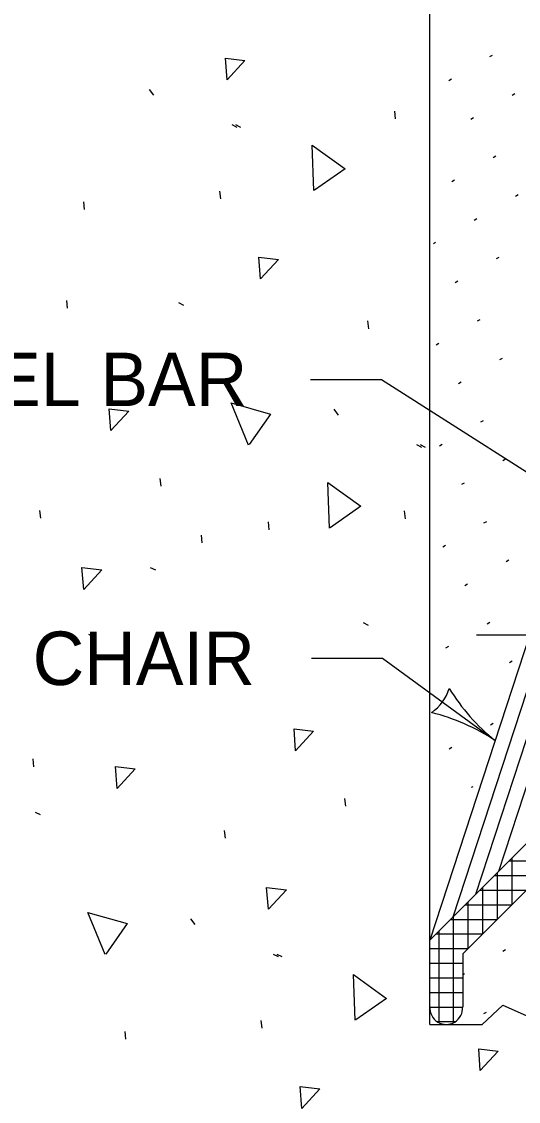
# Model space of a CAD drawing. Extents: x 49991.4 to 50021, y 49987.6 to 50011.4.
# Drawn here: x 50003.117 to 50003.675, y 49989.221 to 49990.433 of the extents above; entities that cross this region are included whole.
import ezdxf

# ---------------------------------------------------------------- set-up
doc = ezdxf.new("R2010")
doc.units = 0
for name, color, linetype in [('Level 1', 7, 'Continuous'), ('Level 2', 7, 'Continuous'), ('Level 3', 7, 'Continuous'), ('Level 4', 7, 'Continuous'), ('Level 6', 7, 'Continuous')]:
    doc.layers.add(name, color=color, linetype=linetype)

msp = doc.modelspace()

# ---------------------------------------------------------------- linework, layer by layer
at = {"layer": 'Level 1'}
for p, q in [((50003.688, 49989.7449), (50003.5758, 49989.4019)), ((50003.6913, 49989.7021), (50003.6015, 49989.4276)), ((50003.6981, 49989.6701), (50003.6271, 49989.4532)), ((50003.7067, 49989.6437), (50003.6528, 49989.4789)), ((50003.5758, 49989.4019), (50003.7465, 49989.5726)), ((50003.7709, 49989.5448), (50003.6127, 49989.3867)), ((50003.6647, 49989.4908), (50003.7169, 49989.4908)), ((50003.6681, 49989.442), (50003.6681, 49989.4942)), ((50003.6483, 49989.4744), (50003.7005, 49989.4744)), ((50003.6517, 49989.4256), (50003.6517, 49989.4778)), ((50003.6353, 49989.4092), (50003.6353, 49989.4614)), ((50003.6319, 49989.458), (50003.684, 49989.458)), ((50003.6155, 49989.4416), (50003.6676, 49989.4416)), ((50003.6189, 49989.3928), (50003.6189, 49989.445)), ((50003.5991, 49989.4252), (50003.6512, 49989.4252)), ((50003.6025, 49989.3091), (50003.6025, 49989.4286)), ((50003.5861, 49989.3091), (50003.5861, 49989.4122)), ((50003.5758, 49989.3268), (50003.5758, 49989.4019)), ((50003.5827, 49989.4088), (50003.6348, 49989.4088)), ((50003.5758, 49989.3924), (50003.6184, 49989.3924)), ((50003.5758, 49989.376), (50003.6127, 49989.376)), ((50003.6127, 49989.3867), (50003.6127, 49989.3268)), ((50003.5758, 49989.3596), (50003.6127, 49989.3596)), ((50003.5758, 49989.3432), (50003.6127, 49989.3432)), ((50003.6127, 49989.3268), (50003.6127, 49989.3268)), ((50003.5758, 49989.3268), (50003.6126, 49989.3268)), ((50003.5839, 49989.3104), (50003.6046, 49989.3104))]:
    msp.add_line(p, q, dxfattribs=at)
msp.add_arc((50003.5942, 49989.3257), 0.0184, 176.3757, 3.6243, dxfattribs=at)
at = {"layer": 'Level 3'}
for p, q in [((50003.6432, 49990.3938), (50003.6462, 49990.3955)), ((50003.5969, 49990.367), (50003.5999, 49990.3688)), ((50003.6682, 49990.3505), (50003.6712, 49990.3522)), ((50003.6219, 49990.3237), (50003.6249, 49990.3255)), ((50003.6469, 49990.2804), (50003.6499, 49990.2822)), ((50003.6005, 49990.2536), (50003.6036, 49990.2554)), ((50003.6719, 49990.2371), (50003.6749, 49990.2389)), ((50003.6255, 49990.2103), (50003.6286, 49990.2121)), ((50003.5797, 49990.1839), (50003.5822, 49990.1853)), ((50003.6505, 49990.167), (50003.6536, 49990.1688)), ((50003.6042, 49990.1403), (50003.6072, 49990.142)), ((50003.6292, 49990.097), (50003.6322, 49990.0987)), ((50003.5829, 49990.0702), (50003.5859, 49990.072)), ((50003.6542, 49990.0537), (50003.6572, 49990.0554)), ((50003.4416, 49990.0314), (50003.5216, 49990.0314)), ((50003.6079, 49990.0269), (50003.6109, 49990.0287)), ((50003.6329, 49989.9836), (50003.6359, 49989.9854)), ((50003.5865, 49989.9569), (50003.5896, 49989.9586)), ((50003.6579, 49989.9403), (50003.6609, 49989.9421)), ((50003.6115, 49989.9136), (50003.6146, 49989.9153)), ((50003.6365, 49989.8703), (50003.6396, 49989.872)), ((50003.5902, 49989.8435), (50003.5932, 49989.8453)), ((50003.6615, 49989.827), (50003.6646, 49989.8287)), ((50003.6152, 49989.8002), (50003.6182, 49989.802)), ((50003.6402, 49989.7569), (50003.6432, 49989.7587)), ((50003.628, 49989.7448), (50004.627, 49989.7448)), ((50003.5938, 49989.7302), (50003.5969, 49989.7319)), ((50003.4427, 49989.7183), (50003.5227, 49989.7183)), ((50003.6652, 49989.7136), (50003.6682, 49989.7154)), ((50003.6438, 49989.6436), (50003.6469, 49989.6453)), ((50003.5975, 49989.6168), (50003.6005, 49989.6186)), ((50003.6225, 49989.5735), (50003.6243, 49989.5745)), ((50003.6578, 49989.3895), (50003.6609, 49989.3912)), ((50003.6127, 49989.3635), (50003.6145, 49989.3645)), ((50003.6365, 49989.3194), (50003.6395, 49989.3212))]:
    msp.add_line(p, q, dxfattribs=at)
for points in [[(50003.5216, 49990.0314), (50003.7637, 49989.877)], [(50003.5227, 49989.7183), (50003.6491, 49989.6259)]]:
    msp.add_lwpolyline(points, dxfattribs=at)
for centre, radius, start, end in [((50003.5456, 49989.7016), 0.0548, 305.9778, 341.7002), ((50003.7876, 49989.7999), 0.2223, 211.295, 231.4785), ((50003.5211, 49989.4313), 0.233, 56.6663, 75.9162)]:
    msp.add_arc(centre, radius, start, end, dxfattribs=at)
at = {"layer": 'Level 4'}
for p, q in [((50003.2605, 49990.357), (50003.2653, 49990.3505)), ((50003.5372, 49990.324), (50003.5363, 49990.3327)), ((50003.3534, 49990.3174), (50003.3591, 49990.3146)), ((50003.3575, 49990.3174), (50003.3632, 49990.3146)), ((50003.3409, 49990.2342), (50003.34, 49990.2429)), ((50003.188, 49990.222), (50003.1871, 49990.2307)), ((50003.1689, 49990.1113), (50003.1679, 49990.12)), ((50003.2934, 49990.1176), (50003.2991, 49990.1147)), ((50003.5072, 49990.0883), (50003.5063, 49990.097)), ((50003.4679, 49989.9978), (50003.4727, 49989.9913)), ((50003.5608, 49989.9582), (50003.5665, 49989.9553)), ((50003.5649, 49989.9582), (50003.5706, 49989.9554)), ((50003.2739, 49989.9115), (50003.273, 49989.9202)), ((50003.1388, 49989.8756), (50003.1379, 49989.8843)), ((50003.5483, 49989.875), (50003.5474, 49989.8837)), ((50003.3954, 49989.8627), (50003.3945, 49989.8714)), ((50003.3202, 49989.8479), (50003.3193, 49989.8566)), ((50003.2617, 49989.8203), (50003.2675, 49989.8175)), ((50003.5008, 49989.7583), (50003.5065, 49989.7555)), ((50003.1924, 49989.7455), (50003.1981, 49989.7427)), ((50003.1311, 49989.5966), (50003.1301, 49989.6053)), ((50003.4813, 49989.5523), (50003.4804, 49989.561)), ((50003.1324, 49989.5457), (50003.1382, 49989.5428)), ((50003.3463, 49989.5163), (50003.3453, 49989.525)), ((50003.307, 49989.4258), (50003.3117, 49989.4194)), ((50003.3998, 49989.3863), (50003.4055, 49989.3834)), ((50003.4039, 49989.3863), (50003.4096, 49989.3834)), ((50003.3873, 49989.303), (50003.3864, 49989.3117)), ((50003.2345, 49989.2908), (50003.2335, 49989.2995))]:
    msp.add_line(p, q, dxfattribs=at)
for points in [[(50003.348, 49990.3676), (50003.3461, 49990.3922), (50003.3681, 49990.3895), (50003.348, 49990.3676)], [(50003.4454, 49990.2433), (50003.4435, 49990.2945), (50003.4805, 49990.2677), (50003.4462, 49990.2437)], [(50003.3857, 49990.1442), (50003.3838, 49990.1688), (50003.4059, 49990.1661), (50003.3857, 49990.1442)], [(50003.2176, 49989.9739), (50003.2158, 49989.9984), (50003.2378, 49989.9958), (50003.2176, 49989.9739)], [(50003.3721, 49989.9576), (50003.3528, 49990.0051), (50003.3968, 49989.9925), (50003.3727, 49989.9583)], [(50003.4631, 49989.8645), (50003.4613, 49989.9157), (50003.4983, 49989.8889), (50003.4639, 49989.8649)], [(50003.187, 49989.7957), (50003.1851, 49989.8203), (50003.2072, 49989.8176), (50003.187, 49989.7957)], [(50003.425, 49989.6146), (50003.4232, 49989.6392), (50003.4452, 49989.6365), (50003.425, 49989.6146)], [(50003.2247, 49989.5723), (50003.2228, 49989.5968), (50003.2449, 49989.5942), (50003.2247, 49989.5723)], [(50003.3944, 49989.4365), (50003.3925, 49989.461), (50003.4146, 49989.4584), (50003.3944, 49989.4365)], [(50003.2111, 49989.3857), (50003.1918, 49989.4331), (50003.2358, 49989.4206), (50003.2117, 49989.3863)], [(50003.4918, 49989.3121), (50003.49, 49989.3633), (50003.527, 49989.3365), (50003.4926, 49989.3126)], [(50003.6324, 49989.2554), (50003.6306, 49989.28), (50003.6526, 49989.2773), (50003.6324, 49989.2554)], [(50003.4321, 49989.213), (50003.4303, 49989.2376), (50003.4523, 49989.2349), (50003.4321, 49989.213)]]:
    msp.add_lwpolyline(points, dxfattribs=at)
at = {"layer": 'Level 6'}
for p, q in [((50003.5758, 49989.9969), (50003.5758, 49990.8781)), ((50003.5758, 49989.3073), (50003.5758, 49989.9969)), ((50003.5758, 49989.3073), (50003.6346, 49989.3073))]:
    msp.add_line(p, q, dxfattribs=at)
msp.add_lwpolyline([(50003.6346, 49989.3073), (50003.6578, 49989.329), (50003.6939, 49989.3127)], dxfattribs=at)

# ---------------------------------------------------------------- texts
at = {"layer": 'Level 2'}
for s, p in [('DOWEL BAR', (50002.8893, 49990.0014)), ('CHAIR', (50003.1297, 49989.6883))]:
    msp.add_text(s, height=0.06, dxfattribs=at).set_placement(p)

doc.saveas('drawing.dxf')
